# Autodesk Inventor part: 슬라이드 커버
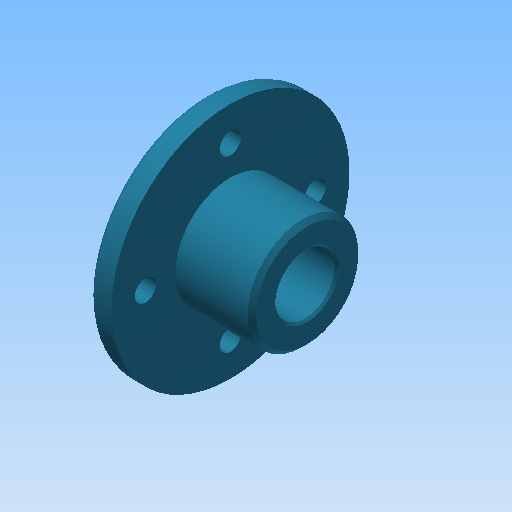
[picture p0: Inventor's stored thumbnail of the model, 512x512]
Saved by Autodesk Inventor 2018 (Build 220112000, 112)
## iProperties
Created: 2015-12
Part Number: 슬라이드 커버
Document SubType Name: Modeling
Designer: mdu
Density: 2.71 g/cm^3
Material: 알루미늄 6061
Mass: 53.5737 g
Surface Area: 81.0277 cm^2
Volume: 19.7689 cm^3
Appearance: 터키옥색
Author: mdu
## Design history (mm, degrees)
sketch "스케치1"
  geometry: L1 (-12, 0)-(12, 0); L2 (-12, 0)-(-12, 28); L3 (-12, 28)-(-6, 28); L4 (-6, 28)-(-6, 13); L5 (-6, 13)-(12, 13); L6 (12, 13)-(12, 0); 2 further points
  constraints: 12 end point, 3 perpendicular, 1 coincident, 1 horizontal, 1 midpoint, 1 parallel
  dimensions: "d1" = 56 diameter of L3 L1; "d2" = 26 diameter of L5 L1; "d5" = 6 distance of L2.end L3.end; "d32" = 18 distance of L4.end L5.end
revolve "회전1" sketch "스케치1" stored, may be unused: angle "d6" = 90 deg
sketch "스케치2" dims "d33" = 40
  geometry: 3 further points
  constraints: 2 vertical alignment, 1 coincident, 2 other
hole "구멍1" sketch "스케치2" at (0, 20) diameter "d8" = 5; stored, may be unused: countersink angle "d12" = 90 deg, drill point angle "d14" = 118 deg; dims "d9" = 6, "d10" = 8, "d11" = 4.4, "d13" = 8
hole "구멍2" diameter "d20" = 14; stored, may be unused: countersink angle "d24" = 90 deg, drill point angle "d26" = 0 deg; dims "d18" = 10, "d19" = 10, "d21" = 6, "d22" = 8, "d23" = 4.4, "d25" = 8
fillet "모깎기1" dims "d27" = 3
chamfer "모따기1" distance "d29" = 1; stored, may be unused: second distance "d30" = 2, angle "d31" = 45 deg
chamfer "모따기2" distance "d35" = 0.5; stored, may be unused: second distance "d36" = 2, angle "d37" = 45 deg
node "솔리드1"
pattern_circular "원형 패턴1" dims angle "d16" = 360 deg
